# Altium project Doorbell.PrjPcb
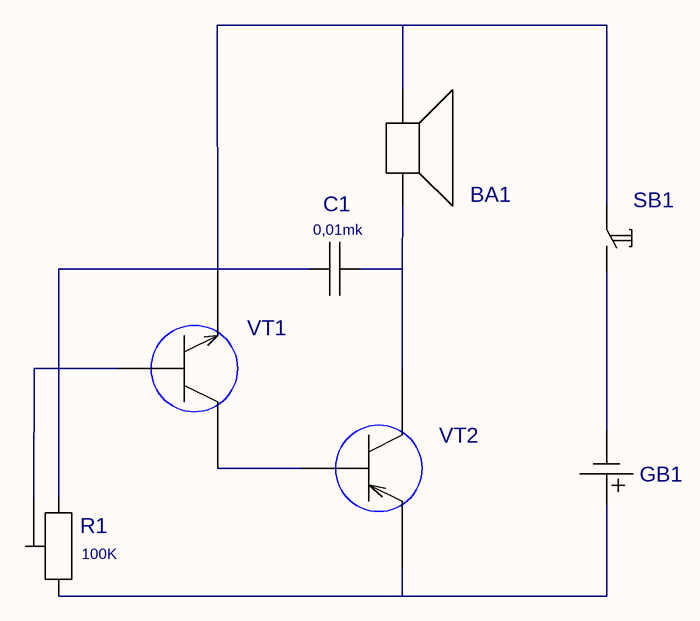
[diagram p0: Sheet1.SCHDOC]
1 sheet, 7 parts. Net scope: global (net labels, ports and power ports of the same name join across sheets).
Board file: Doorbell.PcbDoc

## Sheet Sheet1.SCHDOC
size 297 x 209 mm; SheetNumber: 1; SheetTotal: 1

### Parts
BA1  0,25ГД-10  [0,25ГД-10]  (value not drawn)
C1  value 0,01mk  [K1017-2]  (hidden comment: K1017-2)
GB1  BH-624 (1X AAA)  [BH-624 (1X AAA)]  (value not drawn)
R1  value 100K  [SP3-19A1]  (hidden comment: SP3-19A1)
SB1  KAN1210-0731B  [KAN1210-0731B]  (value not drawn)
VT1  КТ315Г  [KT13]  (value not drawn)
VT2  КТ814А  [KT-27]  (value not drawn)

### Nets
NetBA1_1: BA1.1 C1.2(I/OB) VT2.2(K)
NetBA1_2: BA1.2 C1.1(I/OA) R1.2(I/O2) R1.3(I/O3) SB1.1 VT1.1(E) VT1.2(B)
NetGB1_1: GB1.1 SB1.3
NetGB1_2: GB1.2 R1.1(I/O1) VT2.1(E)
NetVT1_3: VT1.3(K) VT2.3(B)

Not connected (* = marked no-connect by the designer): BA1 3 4 5 6; SB1 2 4

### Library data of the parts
C1 = K1017-2: PDIF_TY: 11213
R1 = SP3-19A1: PDIF_TY: 11107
